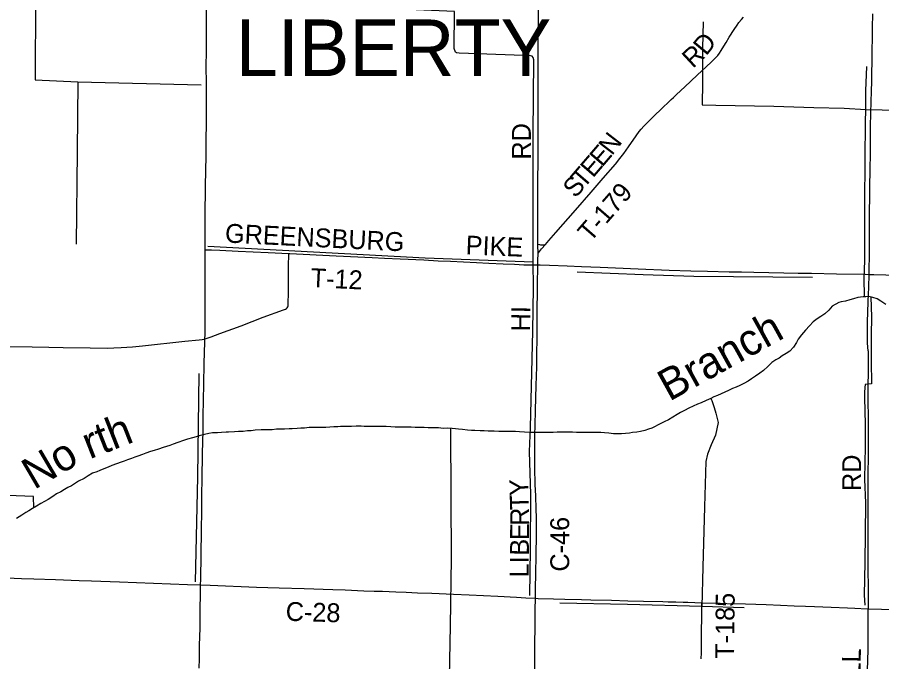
# Model space of a CAD drawing. Extents: x 0 to 680, y 0 to 834.
# Drawn here: x 166.4 to 266.4, y 148.8 to 223.2 of the extents above; entities that cross this region are included whole.
import ezdxf

# ---------------------------------------------------------------- set-up
doc = ezdxf.new("R2010")
doc.units = 0
for name, color, linetype in [('GM_X_County_Road', 7, 'Continuous'), ('GM_X_County_Road_Text', 7, 'Continuous'), ('GM_X_Major_River', 7, 'Continuous'), ('GM_X_Major_River_Text', 7, 'Continuous'), ('GM_X_Minor_River', 7, 'Continuous'), ('GM_X_Township_Road', 7, 'Continuous'), ('GM_X_Township_Road_Text', 7, 'Continuous'), ('GM_X_Township_Text', 7, 'Continuous')]:
    doc.layers.add(name, color=color, linetype=linetype)

msp = doc.modelspace()

# ---------------------------------------------------------------- linework, layer by layer
at = {"layer": 'GM_X_County_Road'}
for points in [[(226.646, 196.73), (226.644, 196.999), (226.643, 197.271), (226.626, 199.181), (226.614, 200.971), (226.62, 203.358), (226.653, 207.654), (226.666, 210.519), (226.66, 213.742), (226.658, 214.935), (226.657, 216.606), (226.665, 219.59), (226.69, 222.335), (226.719, 225.2), (226.767, 228.422), (226.783, 230.57), (226.786, 232.958), (226.786, 233.068)], [(226.647, 195.703), (226.648, 195.97), (226.649, 196.077), (226.646, 196.73)], [(226.622, 194.347), (226.628, 194.617), (226.644, 195.361), (226.647, 195.703)], [(226.346, 155.823), (226.351, 156.089), (226.372, 157.174), (226.395, 158.965), (226.425, 160.993), (226.461, 163.5), (226.467, 165.41), (226.448, 166.366), (226.385, 167.916), (226.336, 169.228), (226.291, 171.137), (226.273, 173.523), (226.29, 174.955), (226.305, 176.029), (226.346, 177.818), (226.44, 180.681), (226.507, 182.829), (226.53, 184.381), (226.54, 186.052), (226.553, 188.439), (226.581, 192.497), (226.622, 194.347)], [(148.928, 158.975), (149.737, 158.957), (151.645, 158.887), (153.196, 158.84), (154.746, 158.782), (156.292, 158.746), (159.995, 158.628), (161.427, 158.581), (164.289, 158.48), (166.913, 158.38), (168.345, 158.337), (170.85, 158.251), (173.593, 158.144), (175.024, 158.089), (178.244, 157.968), (186.117, 157.683), (187.641, 157.623)], [(187.641, 157.623), (188.74, 157.579), (194.107, 157.375), (196.732, 157.295), (199.594, 157.195), (202.934, 157.087), (204.366, 157.047), (206.513, 156.958), (207.705, 156.92), (208.66, 156.891), (210.21, 156.826), (211.403, 156.781), (212.714, 156.727), (214.384, 156.675), (216.888, 156.564), (218.676, 156.471), (222.014, 156.314), (224.16, 156.207), (225.233, 156.15), (226.351, 156.089)], [(226.351, 156.089), (226.662, 156.072), (228.451, 156.01), (229.763, 155.983), (231.672, 155.944), (232.746, 155.916), (235.132, 155.851), (237.041, 155.798), (238.831, 155.748), (241.098, 155.69), (241.712, 155.674), (242.599, 155.651), (243.438, 155.63), (243.97, 155.617), (244.797, 155.596), (245.603, 155.567)], [(226.196, 141.451), (226.199, 141.713), (226.218, 143.211), (226.233, 145.002), (226.251, 146.314), (226.262, 147.985), (226.287, 150.133), (226.31, 153.476), (226.324, 154.549), (226.33, 155.027), (226.346, 155.823)], [(245.603, 155.567), (247.301, 155.507), (248.494, 155.475), (250.642, 155.419), (253.028, 155.347), (254.698, 155.285), (256.247, 155.223), (257.558, 155.18), (258.632, 155.145), (260.54, 155.069), (262.447, 154.981), (263.281, 154.94), (264.712, 154.873), (264.846, 154.87)], [(264.846, 154.87), (266.381, 154.814), (268.171, 154.759), (270.915, 154.707), (273.182, 154.673), (275.33, 154.639), (275.926, 154.624), (276.642, 154.609), (277.477, 154.592), (277.596, 154.589), (277.954, 154.574), (279.625, 154.533), (283.443, 154.417), (285.948, 154.342), (287.976, 154.27), (291.434, 154.148), (293.582, 154.09), (294.774, 154.056), (295.847, 154.037), (296.8, 154.016), (297.749, 153.986), (298.739, 153.968)]]:
    msp.add_lwpolyline(points, dxfattribs=at)
at = {"layer": 'GM_X_Major_River'}
for points in [[(266.869, 190.042), (266.301, 190.408), (265.865, 190.672), (265.37, 190.834), (264.89, 190.952), (264.543, 190.936), (264.233, 190.925), (263.624, 190.825), (263.112, 190.695), (262.703, 190.565), (262.193, 190.435), (261.683, 190.349), (261.419, 190.248), (260.661, 189.842), (260.267, 189.391), (259.799, 188.954), (259.346, 188.635), (258.923, 188.359), (258.47, 188.025), (258.032, 187.56), (257.579, 187.05), (257.096, 186.527), (256.73, 186.032), (256.54, 185.639), (256.203, 185.115), (255.75, 184.635), (255.341, 184.359), (254.889, 184.083), (254.524, 183.822), (254.144, 183.619), (253.677, 183.314), (253.209, 182.863), (252.713, 182.412), (252.289, 182.107), (251.793, 181.759), (251.325, 181.454), (250.946, 181.178), (250.435, 180.902), (249.968, 180.685), (249.574, 180.497), (249.136, 180.323), (248.67, 180.091), (248.232, 179.902), (247.823, 179.714), (247.386, 179.526), (246.992, 179.367), (246.627, 179.164), (246.073, 178.932), (245.518, 178.686), (245.081, 178.512), (244.599, 178.28), (244.088, 178.033), (243.592, 177.787), (243.14, 177.555), (242.746, 177.337), (242.22, 177.003), (241.739, 176.713), (241.228, 176.481), (240.834, 176.278), (239.813, 175.756), (239.433, 175.612), (238.996, 175.467), (238.485, 175.352), (238.092, 175.28), (237.582, 175.223), (237.217, 175.181), (236.773, 175.138), (236.285, 175.104), (235.875, 175.082), (235.367, 175.099), (234.843, 175.159), (234.347, 175.204), (233.925, 175.22), (233.386, 175.236), (232.541, 175.238), (232.002, 175.254), (231.463, 175.242), (231.099, 175.257), (230.632, 175.259), (230.224, 175.274), (229.802, 175.29), (229.248, 175.277), (228.855, 175.264), (228.418, 175.236), (227.879, 175.223), (227.485, 175.239), (227.121, 175.24), (226.713, 175.226), (225.664, 175.23), (225.067, 175.275)], [(225.067, 175.275), (224.497, 175.321), (224.031, 175.343), (223.644, 175.342), (223.267, 175.353), (222.867, 175.369), (222.109, 175.371), (221.572, 175.375), (221.239, 175.386), (220.896, 175.397), (220.43, 175.43), (219.976, 175.44), (219.356, 175.451), (218.963, 175.483), (218.482, 175.513), (217.914, 175.573), (217.463, 175.633), (217.099, 175.678), (216.705, 175.708), (216.152, 175.725), (215.671, 175.711), (215.123, 175.76), (214.403, 175.77), (213.937, 175.76), (213.486, 175.805), (212.976, 175.807), (212.437, 175.823), (211.971, 175.839), (211.478, 175.841), (211.046, 175.863), (210.425, 175.863), (210.149, 175.859), (209.64, 175.904), (209.072, 175.92), (208.562, 175.936), (208.023, 175.924), (207.545, 175.95), (206.957, 175.95), (206.536, 175.949), (206.216, 175.958), (205.617, 175.96), (205.094, 175.932), (204.686, 175.919), (204.205, 175.92), (203.811, 175.915), (203.489, 175.904), (203.035, 175.881), (202.581, 175.859), (202.107, 175.81), (201.568, 175.811), (201.029, 175.827), (200.65, 175.814), (200.198, 175.801), (199.659, 175.758), (199.236, 175.731), (198.785, 175.703), (198.231, 175.675), (197.867, 175.647), (197.342, 175.634), (196.876, 175.621), (196.424, 175.608), (195.914, 175.565), (194.648, 175.528), (193.947, 175.498), (193.466, 175.441), (193.043, 175.413), (192.562, 175.371), (192.023, 175.343), (191.572, 175.316), (190.848, 175.288), (190.582, 175.271), (190.05, 175.227), (189.584, 175.216), (189.008, 175.193), (188.584, 175.135), (188.074, 175.005), (187.457, 174.838), (187.136, 174.749), (186.703, 174.63), (186.105, 174.456), (185.639, 174.326), (185.011, 174.095), (184.457, 173.878), (184.092, 173.748), (183.684, 173.617), (183.29, 173.487), (182.78, 173.299), (182.284, 173.14), (181.846, 173.025), (181.307, 172.851), (180.898, 172.692), (180.388, 172.504), (180.035, 172.375), (179.629, 172.229), (179.192, 172.07), (178.798, 171.911), (178.433, 171.795), (177.923, 171.607), (177.369, 171.419), (176.931, 171.245), (176.445, 171.055)], [(176.445, 171.055), (175.98, 170.866), (175.618, 170.709), (175.149, 170.522), (174.64, 170.245), (174.159, 169.941), (173.531, 169.607), (173.064, 169.302), (172.699, 169.084), (172.276, 168.881), (171.897, 168.664), (171.459, 168.373), (170.992, 168.141), (170.568, 167.851), (170.013, 167.502), (169.567, 167.251), (169.167, 167.038), (168.656, 166.719), (168.193, 166.464), (167.761, 166.198), (167.415, 165.978), (166.977, 165.702), (166.35, 165.281)]]:
    msp.add_lwpolyline(points, dxfattribs=at)
at = {"layer": 'GM_X_Minor_River'}
for points in [[(144.423, 235.642), (149.639, 235.452), (155.904, 235.433), (168.578, 235.134), (168.549, 225.435), (168.49, 215.999), (173.428, 215.751), (187.706, 215.418)], [(225.693, 156.4), (225.768, 161.709), (225.817, 168.082), (225.672, 173.027), (225.797, 175.827), (226.05, 186.969), (226.139, 191.986), (226.104, 194.918), (226.093, 209.736), (226.163, 218.326), (226.106, 218.56), (225.975, 218.735), (225.771, 218.78), (224.97, 218.811), (217.541, 219.095), (217.235, 219.125), (217.089, 219.213), (216.945, 219.607), (217.002, 223.895), (207.227, 224.332), (207.416, 233.725), (190.809, 234.443)], [(245.729, 222.703), (245.676, 219.669), (245.678, 215.687), (245.626, 213.106), (247.214, 213.072), (253.915, 212.95), (258.548, 212.805), (262.03, 212.707), (264.535, 212.583), (268.338, 212.499), (275.417, 212.186), (281.885, 211.933), (289.082, 211.634), (294.021, 211.473), (301.086, 211.306), (305.632, 211.249), (314.33, 211.106), (322.037, 211.069), (325.563, 211.029), (330.269, 210.957), (332.687, 210.877), (334.85, 210.826)], [(264.38, 190.93), (264.358, 193.127), (264.437, 195.096), (264.42, 198.975), (264.443, 201.601), (264.488, 206.836), (264.501, 211.081), (264.535, 212.583), (264.571, 214.727), (264.667, 217.542)], [(173.428, 215.751), (173.345, 207.73), (173.238, 197.012)], [(226.104, 194.918), (213.591, 195.392), (197.101, 196.286), (188.463, 196.72)], [(231.171, 193.794), (238.804, 193.509), (244.675, 193.288), (258.37, 193.188)], [(265.122, 190.895), (265.189, 188.588), (265.167, 186.488), (265.173, 183.498), (265.208, 180.858), (264.465, 180.802), (264.42, 180.423), (264.389, 179.869), (264.402, 179.3), (264.48, 176.178), (264.457, 173.495), (264.451, 171.803), (264.416, 169.819), (264.495, 167.121), (264.469, 163.547), (264.43, 160.236), (264.375, 156.429), (264.429, 155.291)], [(187.06, 157.986), (187.316, 170.106), (187.484, 182.065)], [(246.627, 179.164), (246.744, 178.935), (247.017, 178.112), (247.205, 177.484), (247.493, 176.39), (247.167, 174.918), (246.654, 173.796), (246.257, 172.747), (246.065, 171.887), (245.903, 166.651), (245.707, 159.665), (245.591, 155.129)], [(216.53, 175.713), (216.549, 167.731), (216.615, 160.671), (216.489, 152.882), (216.334, 144.962), (216.15, 137.1), (208.91, 137.428), (200.651, 137.89), (193.207, 138.232), (189.623, 138.403), (187.494, 137.694), (186.954, 137.346), (186.876, 130.898), (186.708, 123.182), (186.756, 119.841), (186.841, 119.082), (186.843, 114.603), (186.799, 109.717), (186.742, 100.482)], [(168.336, 166.542), (168.295, 167.857), (158.345, 168.236), (148.424, 168.527), (145.846, 168.593)], [(250.486, 154.983), (245.591, 155.129), (236.981, 155.359), (229.187, 155.529)]]:
    msp.add_lwpolyline(points, dxfattribs=at)
at = {"layer": 'GM_X_Township_Road'}
for points in [[(188.154, 196.359), (188.153, 196.7), (188.172, 198.133), (188.171, 200.162), (188.208, 203.743), (188.266, 207.204), (188.289, 209.114), (188.318, 210.904), (188.313, 213.769), (188.311, 215.56), (188.296, 217.589), (188.298, 219.26), (188.311, 220.812), (188.313, 222.722), (188.339, 225.945), (188.353, 227.497), (188.348, 229.884), (188.329, 231.913), (188.323, 233.465), (188.313, 234.946)], [(227.516, 196.977), (227.917, 197.438), (228.697, 198.341), (230.971, 200.949), (232.782, 203.012), (234.193, 204.632), (235.597, 206.258), (236.128, 206.902), (236.563, 207.471), (237.116, 208.249), (237.993, 209.529), (238.342, 210.013), (238.566, 210.292), (238.884, 210.647), (239.217, 210.989), (240.251, 211.979), (240.77, 212.473), (242.057, 213.718), (242.32, 213.961), (242.665, 214.29), (243.633, 215.176), (244.314, 215.844), (245.092, 216.585), (246.065, 217.466), (246.762, 218.118), (247.185, 218.539), (247.422, 218.806), (247.641, 219.089), (247.842, 219.386), (248.151, 219.896), (248.4, 220.303), (248.767, 220.918), (249.336, 221.829), (249.659, 222.327), (249.869, 222.617), (250.168, 222.988), (250.408, 223.254)], [(264.925, 193.506), (264.927, 193.579), (264.953, 194.522), (264.974, 195.24), (264.982, 195.55), (264.981, 196.84), (264.987, 197.985), (264.993, 199.394), (264.99, 200.396), (265.01, 202.831), (265.027, 203.988), (265.046, 205.238), (265.057, 205.981), (265.076, 207.127), (265.079, 207.58), (265.087, 208.535), (265.088, 209.61), (265.101, 210.588), (265.127, 212.14), (265.178, 213.452), (265.214, 214.692), (265.233, 215.79), (265.25, 216.673), (265.27, 218.201), (265.288, 219.418), (265.307, 220.803), (265.322, 222.02), (265.354, 223.62)], [(226.644, 196.999), (226.814, 196.955), (226.939, 196.922), (227.067, 196.914), (227.196, 196.923), (227.322, 196.944), (227.516, 196.977)], [(226.648, 195.97), (226.824, 196.175), (227.057, 196.447), (227.516, 196.977)], [(188.14, 186.058), (188.153, 186.554), (188.16, 187.987), (188.15, 189.896), (188.16, 193.955), (188.158, 195.387), (188.154, 196.359)], [(188.14, 186.058), (188.278, 186.098), (188.843, 186.291), (189.85, 186.663), (192.311, 187.579), (194.876, 188.554), (197.228, 189.422), (197.451, 189.511), (197.554, 189.569), (197.643, 189.646), (197.708, 189.743), (197.749, 189.856), (197.769, 189.973), (197.776, 190.092), (197.784, 191.405), (197.807, 193.553), (197.812, 194.747), (197.825, 195.582), (197.83, 195.924)], [(188.154, 196.359), (188.41, 196.358), (188.887, 196.355), (189.841, 196.322), (191.986, 196.211), (195.443, 196.045), (197.83, 195.924)], [(197.83, 195.924), (197.946, 195.918), (203.311, 195.672), (207.483, 195.474), (208.913, 195.399), (210.702, 195.317), (213.443, 195.181), (215.112, 195.092), (216.542, 195.026), (219.522, 194.888), (220.953, 194.817), (222.622, 194.746), (223.933, 194.682), (225.006, 194.634), (225.841, 194.616), (226.628, 194.617)], [(226.628, 194.617), (226.915, 194.617), (227.988, 194.581), (230.015, 194.494), (231.684, 194.419), (233.83, 194.334), (235.619, 194.255), (238.242, 194.143), (241.82, 194.007), (244.324, 193.933), (246.233, 193.871), (248.738, 193.824), (250.17, 193.799), (251.602, 193.773), (255.062, 193.706), (256.733, 193.672), (258.284, 193.639), (261.148, 193.589), (264.488, 193.519), (264.925, 193.506)], [(264.846, 154.87), (264.847, 157.656), (264.843, 158.014), (264.831, 158.706), (264.822, 159.636), (264.823, 160.973), (264.833, 162.525), (264.837, 164.841), (264.834, 166.822), (264.832, 167.849), (264.834, 168.851), (264.839, 170.331), (264.845, 172.599), (264.844, 173.267), (264.843, 174.246), (264.851, 175.32), (264.853, 176.06), (264.842, 177.35), (264.834, 178.495), (264.836, 179.856), (264.824, 180.691), (264.844, 182.124), (264.856, 182.887), (264.868, 183.627), (264.855, 184.176), (264.849, 184.411), (264.842, 184.605), (264.835, 184.699), (264.795, 185.054), (264.768, 185.282), (264.758, 185.366), (264.752, 185.48), (264.749, 185.574), (264.743, 185.771), (264.751, 186.916), (264.763, 188.157), (264.781, 189.04), (264.834, 190.447), (264.856, 191.183), (264.881, 192.027), (264.925, 193.506)], [(264.925, 193.506), (265.465, 193.491), (266.873, 193.452), (268.424, 193.409), (271.525, 193.303), (274.746, 193.203), (276.058, 193.164), (278.086, 193.086), (280.59, 192.993), (282.26, 192.939), (284.526, 192.868), (285.719, 192.832), (287.747, 192.78), (289.655, 192.71), (291.325, 192.662), (292.757, 192.619), (294.903, 192.543), (296.931, 192.473), (299.436, 192.388), (302.656, 192.272), (303.61, 192.24), (304.165, 192.233)], [(165.551, 185.163), (168.176, 185.121), (170.085, 185.087), (171.755, 185.049), (174.857, 185.01), (176.886, 184.997), (177.602, 185.005), (178.436, 185.05), (179.744, 185.158), (180.932, 185.271), (185.798, 185.776), (187.462, 185.933), (187.816, 185.982), (188.049, 186.032), (188.14, 186.058)], [(187.641, 157.623), (187.652, 158.269), (187.691, 161.133), (187.725, 163.879), (187.76, 166.266), (187.787, 168.056), (187.82, 169.846), (187.871, 172.83), (187.92, 175.456), (187.95, 177.126), (188.025, 180.826), (188.061, 183.213), (188.13, 185.719), (188.14, 186.058)], [(187.488, 148.005), (187.506, 149.079), (187.526, 150.63), (187.57, 152.659), (187.589, 154.45), (187.63, 156.956), (187.641, 157.623)], [(245.511, 149.088), (245.548, 149.758), (245.548, 150.73), (245.558, 151.941), (245.578, 154.199), (245.584, 154.955), (245.599, 155.453), (245.603, 155.567)], [(264.532, 135.774), (264.549, 136.252), (264.548, 136.491), (264.561, 137.088), (264.569, 138.403), (264.582, 138.881), (264.605, 139.238), (264.604, 139.358), (264.584, 139.716), (264.626, 142.585), (264.631, 143.66), (264.693, 146.289), (264.715, 146.886), (264.783, 148.798), (264.815, 150.231), (264.816, 150.829), (264.816, 151.546), (264.81, 152.742), (264.822, 153.817), (264.84, 154.62), (264.846, 154.87)]]:
    msp.add_lwpolyline(points, dxfattribs=at)

# ---------------------------------------------------------------- texts
at = {"layer": 'GM_X_County_Road_Text'}
for s, height, rotation, p in [('RD', 2.1818, 90, (225.822, 206.78)), ('HI', 2.1818, 89.41568, (225.726, 186.917)), ('Y', 2.182, 91.67955, (225.558, 167.944)), ('T', 2.182, 91.92507, (225.612, 166.315)), ('R', 2.182, 90.00961, (225.614, 164.445)), ('C-46', 2.1818, 90, (230.252, 159.164)), ('E', 2.182, 89.54418, (225.601, 162.794)), ('B', 2.182, 89.5358, (225.586, 161.002)), ('L', 2.182, 89.53286, (225.566, 158.474)), ('I', 2.182, 89.53165, (225.579, 160.105)), ('C-28', 2.1818, 358.2847, (197.451, 153.487))]:
    msp.add_text(s, height=height, rotation=rotation, dxfattribs=at).set_placement(p)
at = {"layer": 'GM_X_Major_River_Text'}
for s, height, rotation, p in [('Branch', 3.6382, 28.9782, (241.826, 178.781)), ('rth', 3.6384, 21.39233, (174.792, 172.126)), ('No', 3.6384, 30.39218, (168.38, 168.575))]:
    msp.add_text(s, height=height, rotation=rotation, dxfattribs=at).set_placement(p)
at = {"layer": 'GM_X_Township_Road_Text'}
for s, height, rotation, p in [('D', 2.182, 50.36899, (246.078, 218.69)), ('R', 2.182, 42.75571, (244.549, 217.247)), ('N', 2.182, 52.34969, (235.203, 207.161)), ('E', 2.182, 49.39418, (234.063, 205.827)), ('E', 2.182, 49.31376, (232.997, 204.587)), ('T', 2.182, 49.31089, (231.933, 203.349)), ('S', 2.182, 49.30799, (230.973, 202.233)), ('T-179', 2.1818, 48.97337, (232.702, 197.15)), ('GREENSBURG', 2.1818, 357.12709, (190.417, 197.206)), ('PIKE', 2.1818, 357.57243, (218.253, 195.83)), ('T-12', 2.1818, 357.17306, (200.322, 192.054)), ('RD', 2.1818, 90, (264.003, 168.476)), ('T-185', 2.1818, 89.44197, (249.319, 149.078)), ('MITCHELL', 2.1818, 88.7743, (263.682, 135.839))]:
    msp.add_text(s, height=height, rotation=rotation, dxfattribs=at).set_placement(p)
at = {"layer": 'GM_X_Township_Text'}
msp.add_text('LIBERTY', height=6.5455, rotation=0.00001, dxfattribs=at).set_placement((191.693, 216.426))

doc.saveas('drawing.dxf')
